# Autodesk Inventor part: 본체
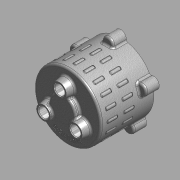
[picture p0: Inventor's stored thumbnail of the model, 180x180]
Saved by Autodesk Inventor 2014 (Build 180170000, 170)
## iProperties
Created: 2015-11
Part Number: 본체
Document SubType Name: 모델링
Designer: mdu
Material: 알루미늄 6061
Density: 2.71 g/cm^3
Appearance: 알루미늄 - 평지
Mass: 487.639 g
Surface Area: 696.801 cm^2
Volume: 179.94 cm^3
변환 표준: STEP AP214IS
파일 이름: C:\Users\SeoGD\Desktop\?쒗뿕\紐몄껜.stp
전처리기: Build: 253, Release: 2010 SP1 - Date: Wed 07/29/2009
전송 단위: 밀리미터
불확실성: 0.01
Author: mdu
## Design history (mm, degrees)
sketch "스케치2"
  geometry: C1 r 50 at (0, 0); 1 further point
  constraints: 1 centre point, 1 coincident
  dimensions: "d9" = 100 diameter of C1
extrude "돌출2" new body sketch "스케치2" distance "d10" = 80; taper "d11" = 0 deg
feature "쉘1" dims "d12" = 5
sketch "스케치3" dims "d13" = 55
  geometry: C1 r 7.5 at (0, 27.5); C2 r 12.5 at (0, 27.5); 2 further points
  constraints: 2 centre point, 2 coincident, 2 vertical alignment, 2 other
  dimensions: "d14" = 15 diameter of C1; "d15" = 25 diameter of C2
extrude "돌출3" join sketch "스케치3" distance "d16" = 12; taper "d17" = -10 deg
hole "구멍2" diameter "d20" = 15; stored, may be unused: countersink angle "d24" = 90 deg, drill point angle "d26" = 118 deg; dims "d18" = 10, "d19" = 10, "d21" = 6, "d22" = 4, "d23" = 2, "d25" = 15
chamfer "모따기1" distance "d27" = 1; stored, may be unused: second distance "d28" = 2, angle "d29" = 45 deg
sketch "스케치4"
  geometry: L1 (0, 0)-(0, 88); L2 (0, 70)-(13.16, 70); L3 (-45, 75)-(45, 75) reference; L4 (-50, 80)-(50, 80) reference; L5 (13.16, 70)-(14.5, 75); L6 (20, 80)-(20, 88); L7 (20, 88)-(0, 88); L8 (20, 80)-(14.5, 75)
  constraints: 12 end point, 3 point on line, 2 perpendicular, 1 vertical
  dimensions: "d34" = 40 diameter of L6 L1; "d35" = 105 deg angle of L5 L3; "d36" = 5 distance between parallel lines of L2 L3; "d37" = 8 distance between parallel lines of L7 L4; "d51" = 29 diameter of L5.end L1
revolve "회전1" sketch "스케치4" stored, may be unused: angle "d38" = 90 deg
hole "구멍3" diameter "d41" = 15; stored, may be unused: countersink angle "d45" = 90 deg, drill point angle "d47" = 0 deg; dims "d39" = 10, "d40" = 10, "d42" = 6, "d43" = 22, "d44" = 13, "d46" = 15
chamfer "모따기2" distance "d48" = 1; stored, may be unused: second distance "d49" = 2, angle "d50" = 45 deg
fillet "모깎기1" dims "d52" = 3
fillet "모깎기2" dims "d53" = 3, "d72" = 0.2
sketch "스케치5"
  geometry: A1 r 50 centre (0, 0) between (50, 0) and (-8.074, 49.344) reference; A2 r 8.5 centre (0, 52) between (8.074, 49.344) and (-8.074, 49.344); 1 further point
  constraints: 5 point on circle, 1 centre point, 1 horizontal alignment
  dimensions: "d54" = 90 deg dimension on point (0, 0) A2.centre A1.start; "d55" = 52 distance of A2.centre point (0, 0); "d56" = 17 diameter of A2
extrude "돌출4" join sketch "스케치5" distance "d57" = 20; taper "d58" = 0 deg
fillet "모깎기3" dims "d59" = 3
hole "구멍4" diameter "d62" = 4.134; stored, may be unused: countersink angle "d66" = 90 deg, drill point angle "d68" = 118 deg; dims "d60" = 10, "d61" = 10, "d63" = 12, "d64" = 22, "d65" = 13, "d67" = 15
sketch "스케치6"
  geometry: C1 r 47 at (0, 0) reference; C2 r 42.5 at (0, 0); 1 further point
  constraints: 1 centre point, 1 coincident, 1 other
  dimensions: "d73" = 85 diameter of C2
feature "엠보싱1" sketch "스케치6" dims "d74" = 0.5, "d75" = 0
node "작업 평면1"
sketch "스케치7"
  geometry: A1 r 50 centre (0, 0) between (5.144, 49.735) and (-5.144, 49.735) reference; A2 r 3 centre (0, 47.916) between (2.204, 49.951) and (-2.204, 49.951); 1 further point
  constraints: 4 point on circle, 1 centre point, 1 vertical alignment
  dimensions: "d77" = 3 radius of A2
extrude "돌출5" join sketch "스케치7" distance "d79" = 15; taper "d80" = 0 deg
fillet "모깎기4" dims "d81" = 1
fillet "모깎기5" dims "d82" = 1
node "솔리드1"
node "솔리드 본체"
node "곡면 본체"
pattern_circular "원형 패턴1" dims "d31" = 360 deg
pattern_circular "원형 패턴2" dims "d70" = 360 deg
pattern_circular "원형 패턴3" dims "d84" = 360 deg
pattern_linear "직사각형 패턴1" dims "d89" = 25
node "솔리드2"
